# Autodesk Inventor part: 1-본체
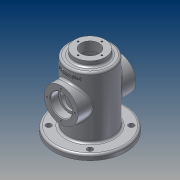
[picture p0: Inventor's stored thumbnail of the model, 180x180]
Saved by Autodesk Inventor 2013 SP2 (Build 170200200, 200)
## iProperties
Created: 2014-12
Part Number: 1-본체
Material: 알루미늄 6061
Document SubType Name: Modeling
Designer: CADB102
Density: 2.71 g/cm^3
Mass: 479.953 g
Surface Area: 609.328 cm^2
Volume: 177.104 cm^3
Author: CADB102
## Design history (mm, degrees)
sketch "스케치1"
  geometry: L1 (0, 51)-(-13.5, 51); L2 (-32.5, 43)-(-32.5, -55); L3 (-32.5, -55)-(-27.5, -55); L4 (0, -55)-(0, 51); L5 (-22.5, 51)-(-22.5, 43); L6 (-22.5, 43)-(-32.5, 43); L7 (0, -55)-(-27.5, -55); L8 (-52.5, -55)-(-52.5, -47); L9 (-52.5, -47)-(-27.5, -47); L10 (0, -47)-(0, -55); L11 (-27.5, -55)-(-27.5, 38); L12 (-27.5, 38)-(-13.5, 38); L13 (-13.5, 38)-(-13.5, 51); L14 (-13.5, 51)-(-22.5, 51); L15 (-27.5, -55)-(-52.5, -55); L16 (-27.5, -47)-(0, -47); L17 (-27.5, -55)-(0, -55); L18 (-13.5, 51)-(0, 51); L19 (-27.5, -55)-(0, -55); 2 further points
  constraints: 38 end point, 12 parallel, 8 perpendicular, 4 horizontal, 2 collinear, 1 midpoint, 1 point on line, 1 vertical alignment
  dimensions: "d4" = 106 distance of L4.start L1.start; "d5" = 45 diameter of L5 L4; "d6" = 65 diameter of L2 L4; "d7" = 105 diameter of L8 L4; "d8" = 8 distance of L8.start L8.end; "d9" = 98 distance between parallel lines of L3 L6; "d10" = 27 diameter of L13 L4; "d11" = 55 diameter of L11 L4; "d12" = 5 distance between parallel lines of L6 L12; "d13" = 55 distance from line of point (0, 0) L7
revolve "회전1" stored, may be unused: angle "d14" = 90 deg
sketch "스케치2"
  geometry: C1 r 25 at (0, 0); 1 further point
  constraints: 1 centre point, 1 coincident
  dimensions: "d15" = 50 diameter of C1
extrude "돌출1" join sketch "스케치2" distance "d16" = 42.5; taper "d17" = 0 deg
hole "구멍1" diameter "d20" = 25; stored, may be unused: countersink angle "d24" = 90 deg, drill point angle "d26" = 118 deg; dims "d18" = 10, "d19" = 10, "d21" = 6, "d22" = 32, "d23" = 12, "d25" = 8
sketch "스케치3"
  geometry: A1 r 20.5 centre (0, 0) between (0, 20.5) and (-20.5, 0); 3 further points
  constraints: 4 point on circle, 2 horizontal alignment, 2 vertical alignment, 1 centre point, 1 coincident
  dimensions: "d27" = 41 diameter of A1
hole "구멍2" sketch "스케치3" at (0, 20.5), (-20.5, 0), (0, -20.5), (20.5, 0) diameter "d29" = 2.459; stored, may be unused: countersink angle "d33" = 90 deg, drill point angle "d35" = 118 deg; dims "d30" = 6, "d31" = 32, "d32" = 12, "d34" = 8
revolve "회전2" stored, may be unused: angle "d36" = 90 deg
sketch "스케치4"
  geometry: A1 r 17.5 centre (0, 0) between (0, 17.5) and (-17.5, 0); 3 further points
  constraints: 4 point on circle, 2 horizontal alignment, 2 vertical alignment, 1 centre point, 1 coincident
  dimensions: "d37" = 35 diameter of A1
hole "구멍3" sketch "스케치4" at (0, 17.5), (-17.5, 0), (0, -17.5), (17.5, 0) diameter "d38" = 2.459; stored, may be unused: countersink angle "d42" = 90 deg, drill point angle "d44" = 118 deg; dims "d39" = 6, "d40" = 32, "d41" = 12, "d43" = 8
sketch "스케치5" dims "d45" = 86
  geometry: L1 (0, 0)-(30.406, 30.406); L2 (0, 0)-(43, 0); 5 further points
  constraints: 4 end point, 2 coincident, 1 equal length, 1 horizontal, 8 other
  dimensions: "d46" = 45 deg angle of L2 L1; "d49" = 360 deg dimension on point (0, 0) point (30.406, 30.406) (derived)
hole "구멍4" sketch "스케치5" at (30.406, 30.406), (-30.406, 30.406), (-30.406, -30.406), (30.406, -30.406) diameter "d51" = 8; stored, may be unused: countersink angle "d55" = 90 deg, drill point angle "d57" = 118 deg; dims "d52" = 6, "d53" = 32, "d54" = 12, "d56" = 8
fillet "모깎기1" dims "d58" = 3
sketch "스케치6"
  geometry: L1 (-29.5, 43)-(29.5, 43) reference; 2 further points
  constraints: 1 vertical alignment, 1 other
  dimensions: "d59" = 9 distance from line of point (0, 34) L1
feature "엠보싱1" sketch "스케치6" dims "d60" = 1, "d61" = 0
fillet "모깎기2" dims "d62" = 0.3
chamfer "모따기1" distance "d63" = 1; stored, may be unused: second distance "d64" = 2, angle "d65" = 45 deg
node "솔리드1"
mirror "대칭1"
